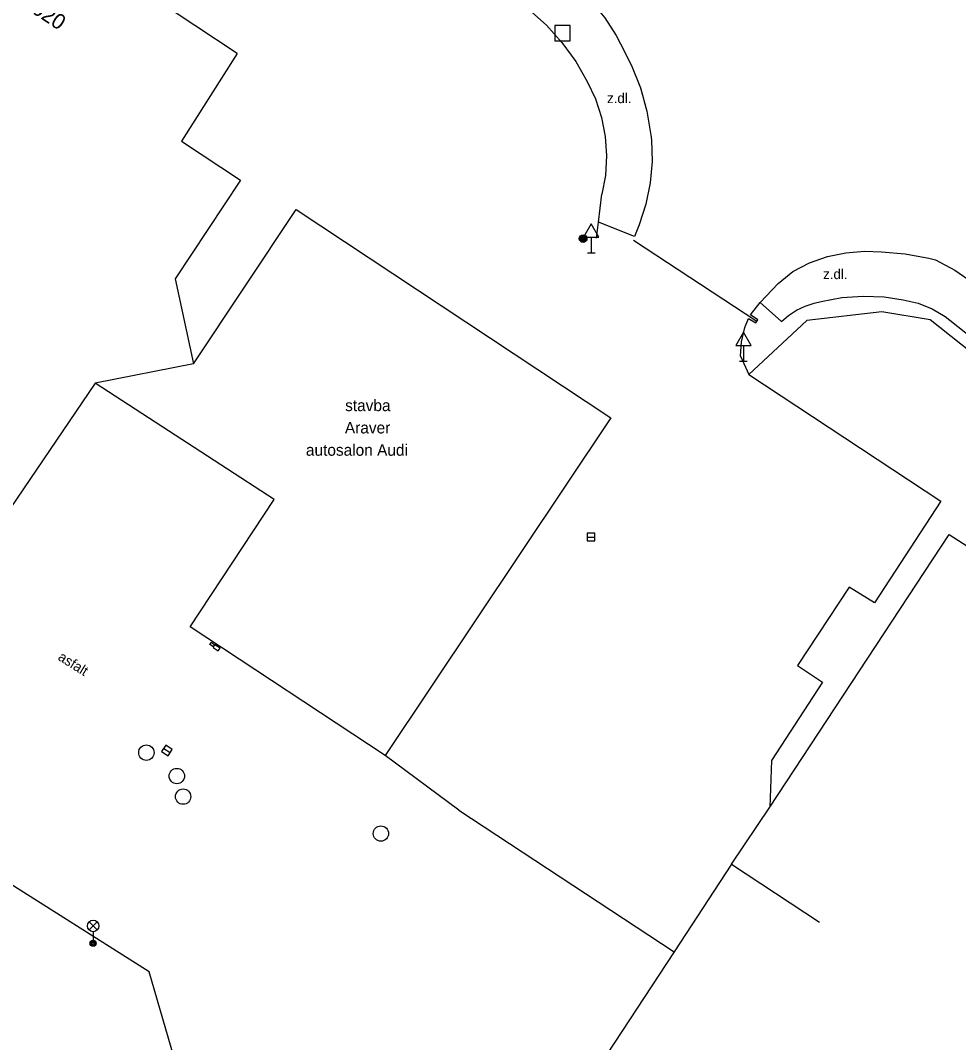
# Model space of a CAD drawing. Extents: x -538441 to -536770, y -1181008 to -1179809.
# Drawn here: x -537975.1 to -537914.1, y -1180448.5 to -1180382.1 of the extents above; entities that cross this region are included whole.
import ezdxf

# ---------------------------------------------------------------- set-up
doc = ezdxf.new("R2010")
doc.units = 0
for name, color, linetype in [('Vrstva 10', 7, 'Continuous'), ('Vrstva 11', 7, 'Continuous'), ('Vrstva 24', 7, 'Continuous'), ('Vrstva 25', 7, 'Continuous'), ('Vrstva 26', 7, 'Continuous'), ('Vrstva 27', 7, 'Continuous'), ('Vrstva 33', 7, 'Continuous'), ('Vrstva 34', 7, 'Continuous'), ('Vrstva 40', 7, 'Continuous'), ('Vrstva 41', 7, 'Continuous'), ('Vrstva 47', 7, 'Continuous'), ('Vrstva 5', 7, 'Continuous'), ('Vrstva 54', 7, 'Continuous'), ('Vrstva 7', 7, 'Continuous'), ('Vrstva 8', 7, 'Continuous')]:
    doc.layers.add(name, color=color, linetype=linetype)

msp = doc.modelspace()

# ---------------------------------------------------------------- linework, layer by layer
at = {"layer": 'Vrstva 10'}
for p, q in [((-537935.16, -1180396.14), (-537937.497, -1180395.219)), ((-537928.25, -1180403.92), (-537927.71, -1180405.109))]:
    msp.add_line(p, q, dxfattribs=at)
for points in [[(-537940.01, -1180379.15), (-537938.927, -1180379.96), (-537937.948, -1180380.893), (-537937.085, -1180381.934), (-537936.351, -1180383.07), (-537936.06, -1180383.62)], [(-537936.06, -1180383.62), (-537935.342, -1180385.018), (-537934.769, -1180386.482), (-537934.348, -1180387.996), (-537934.083, -1180389.546), (-537934.05, -1180389.85)], [(-537934.05, -1180389.85), (-537934.01, -1180391.26), (-537934.13, -1180392.665), (-537934.408, -1180394.047), (-537934.841, -1180395.39), (-537935.16, -1180396.14)], [(-537924.85, -1180398.42), (-537923.763, -1180397.864), (-537922.612, -1180397.454), (-537921.417, -1180397.198), (-537920.2, -1180397.1), (-537919.09, -1180397.15)], [(-537919.09, -1180397.15), (-537917.541, -1180397.271), (-537916.013, -1180397.551), (-537915.58, -1180397.66)], [(-537915.58, -1180397.66), (-537914.316, -1180398.337), (-537913.134, -1180399.151), (-537912.61, -1180399.58)], [(-537927.6, -1180401.24), (-537926.99, -1180400.43), (-537925.812, -1180399.198), (-537924.85, -1180398.42)], [(-537927.73, -1180401.48), (-537927.27, -1180401.75), (-537927.14, -1180401.56), (-537927.6, -1180401.24)], [(-537928.25, -1180403.92), (-537928.187, -1180402.983), (-537927.966, -1180402.069), (-537927.73, -1180401.48)]]:
    msp.add_lwpolyline(points, dxfattribs=at)
at = {"layer": 'Vrstva 11'}
for p, q in [((-537925.6, -1180401.67), (-537926.99, -1180400.43)), ((-537919.07, -1180401.031), (-537923.95, -1180401.594)), ((-537915.92, -1180401.57), (-537919.07, -1180401.031)), ((-537923.95, -1180401.594), (-537927.71, -1180405.109)), ((-537890.449, -1180421.817), (-537915.92, -1180401.57)), ((-537914.64, -1180401.59), (-537906.16, -1180408.34)), ((-537927.71, -1180405.109), (-537915.23, -1180413.352)), ((-537915.23, -1180413.352), (-537919.54, -1180419.969)), ((-537921.2, -1180418.938), (-537924.55, -1180424.039)), ((-537919.54, -1180419.969), (-537921.2, -1180418.938)), ((-537924.55, -1180424.039), (-537922.92, -1180425.109)), ((-537922.92, -1180425.109), (-537926.24, -1180430.219)), ((-537926.24, -1180430.219), (-537926.36, -1180433.242))]:
    msp.add_line(p, q, dxfattribs=at)
for points in [[(-537943.24, -1180380.5), (-537942.011, -1180381.391), (-537940.882, -1180382.407), (-537939.867, -1180383.536), (-537938.976, -1180384.765), (-537938.23, -1180386.06)], [(-537938.23, -1180386.06), (-537937.686, -1180387.202), (-537937.291, -1180388.403), (-537937.051, -1180389.645), (-537936.969, -1180390.907), (-537937.047, -1180392.169), (-537937.28, -1180393.4)], [(-537937.62, -1180396.25), (-537937.497, -1180395.219), (-537937.28, -1180393.4)], [(-537923.02, -1180400.38), (-537921.666, -1180400.118), (-537920.29, -1180400.015), (-537918.912, -1180400.072), (-537917.68, -1180400.26)], [(-537925.6, -1180401.67), (-537925.132, -1180401.27), (-537924.616, -1180400.934), (-537924.061, -1180400.667), (-537923.477, -1180400.474), (-537923.02, -1180400.38)], [(-537917.68, -1180400.26), (-537916.715, -1180400.474), (-537915.798, -1180400.841), (-537914.951, -1180401.351), (-537914.64, -1180401.59)]]:
    msp.add_lwpolyline(points, dxfattribs=at)
at = {"layer": 'Vrstva 24'}
msp.add_line((-537962.52, -1180422.82), (-537962.43, -1180422.68), dxfattribs=at)
for points in [[(-537962.52, -1180422.82), (-537962.77, -1180422.66), (-537962.68, -1180422.52), (-537962.43, -1180422.68)], [(-537962.52, -1180422.82), (-537962.55, -1180422.86), (-537962.22, -1180423.08), (-537962.1, -1180422.9), (-537962.43, -1180422.68)]]:
    msp.add_lwpolyline(points, dxfattribs=at)
at = {"layer": 'Vrstva 25'}
for radius in [0.25, 0.2, 0.15, 0.1, 0.05]:
    msp.add_circle((-537938.49, -1180396.281), radius, dxfattribs=at)
at = {"layer": 'Vrstva 26'}
msp.add_lwpolyline([(-537940.33, -1180383.43), (-537939.33, -1180383.43), (-537939.33, -1180382.43), (-537940.33, -1180382.43)], close=True, dxfattribs=at)
at = {"layer": 'Vrstva 27'}
for p, q in [((-537938.23, -1180415.688), (-537937.73, -1180415.688)), ((-537965.759, -1180429.422), (-537965.341, -1180429.698))]:
    msp.add_line(p, q, dxfattribs=at)
for points in [[(-537938.23, -1180415.938), (-537937.73, -1180415.938), (-537937.73, -1180415.438), (-537938.23, -1180415.438)], [(-537965.896, -1180429.631), (-537965.479, -1180429.906), (-537965.204, -1180429.489), (-537965.621, -1180429.214)]]:
    msp.add_lwpolyline(points, close=True, dxfattribs=at)
for centre in [(-537966.89, -1180429.7), (-537964.91, -1180431.22), (-537964.5, -1180432.56), (-537951.64, -1180434.96)]:
    msp.add_circle(centre, 0.5, dxfattribs=at)
at = {"layer": 'Vrstva 33'}
for p, q in [((-537970.615, -1180441.23), (-537970.085, -1180440.7)), ((-537970.615, -1180440.7), (-537970.085, -1180441.23)), ((-537970.35, -1180441.34), (-537970.35, -1180442.09))]:
    msp.add_line(p, q, dxfattribs=at)
for centre, radius in [((-537970.35, -1180440.965), 0.375), ((-537970.35, -1180442.09), 0.2), ((-537970.35, -1180442.09), 0.145), ((-537970.35, -1180442.09), 0.0876)]:
    msp.add_circle(centre, radius, dxfattribs=at)
at = {"layer": 'Vrstva 34'}
for p, q in [((-537937.96, -1180396.177), (-537937.96, -1180397.195)), ((-537938.21, -1180397.195), (-537937.71, -1180397.195)), ((-537928.07, -1180403.232), (-537928.07, -1180404.25)), ((-537928.32, -1180404.25), (-537927.82, -1180404.25))]:
    msp.add_line(p, q, dxfattribs=at)
for points in [[(-537938.46, -1180396.177), (-537937.46, -1180396.177), (-537937.96, -1180395.311)], [(-537928.57, -1180403.232), (-537927.57, -1180403.232), (-537928.07, -1180402.366)]]:
    msp.add_lwpolyline(points, close=True, dxfattribs=at)
at = {"layer": 'Vrstva 5'}
for p, q in [((-537960.98, -1180384.25), (-537968.046, -1180379.563)), ((-537960.98, -1180384.25), (-537964.602, -1180389.946)), ((-537964.602, -1180389.946), (-537960.77, -1180392.49)), ((-537960.77, -1180392.49), (-537965.02, -1180398.89)), ((-537963.83, -1180404.43), (-537957.16, -1180394.38)), ((-537957.16, -1180394.38), (-537936.7, -1180407.93)), ((-537965.02, -1180398.89), (-537963.83, -1180404.43)), ((-537963.83, -1180404.43), (-537970.22, -1180405.67)), ((-537970.22, -1180405.67), (-537978.44, -1180417.77)), ((-537958.57, -1180413.24), (-537970.22, -1180405.67)), ((-537936.7, -1180407.93), (-537951.36, -1180429.89)), ((-537964.04, -1180421.51), (-537958.57, -1180413.24)), ((-537926.36, -1180433.242), (-537914.69, -1180415.508)), ((-537914.69, -1180415.508), (-537909.15, -1180419.141)), ((-537951.36, -1180429.89), (-537964.04, -1180421.51)), ((-537928.84, -1180436.95), (-537926.36, -1180433.242)), ((-537928.84, -1180436.95), (-537923.126, -1180440.713))]:
    msp.add_line(p, q, dxfattribs=at)
for points in [[(-537928.84, -1180436.95), (-537932.571, -1180442.644)], [(-537932.571, -1180442.644), (-537941.33, -1180455.98)]]:
    msp.add_lwpolyline(points, dxfattribs=at)
at = {"layer": 'Vrstva 54'}
msp.add_line((-537935.22, -1180396.39), (-537927.205, -1180401.655), dxfattribs=at)
at = {"layer": 'Vrstva 7'}
for p, q in [((-537946.58, -1180433.45), (-537932.571, -1180442.644)), ((-537966.7, -1180443.95), (-537982.27, -1180434.1)), ((-537964.631, -1180451.087), (-537966.7, -1180443.95))]:
    msp.add_line(p, q, dxfattribs=at)
at = {"layer": 'Vrstva 8'}
msp.add_line((-537946.58, -1180433.45), (-537951.36, -1180429.89), dxfattribs=at)

# ---------------------------------------------------------------- texts
at = {"layer": 'Vrstva 40'}
for p in [(-537936.939, -1180387.475), (-537922.89, -1180398.916)]:
    msp.add_text('z.dl.', height=0.65, dxfattribs=at).set_placement(p)
msp.add_text('asfalt', height=0.65, rotation=327.90933, dxfattribs=at).set_placement((-537972.691, -1180423.638))
at = {"layer": 'Vrstva 41'}
for s, p in [('stavba', (-537953.966, -1180407.498)), ('Araver', (-537953.982, -1180408.948)), ('autosalon Audi', (-537956.516, -1180410.398))]:
    msp.add_text(s, height=0.75, dxfattribs=at).set_placement(p)
at = {"layer": 'Vrstva 47'}
msp.add_text('2020', height=1, rotation=326.42594, dxfattribs=at).set_placement((-537975.04, -1180381.127))

doc.saveas('drawing.dxf')
